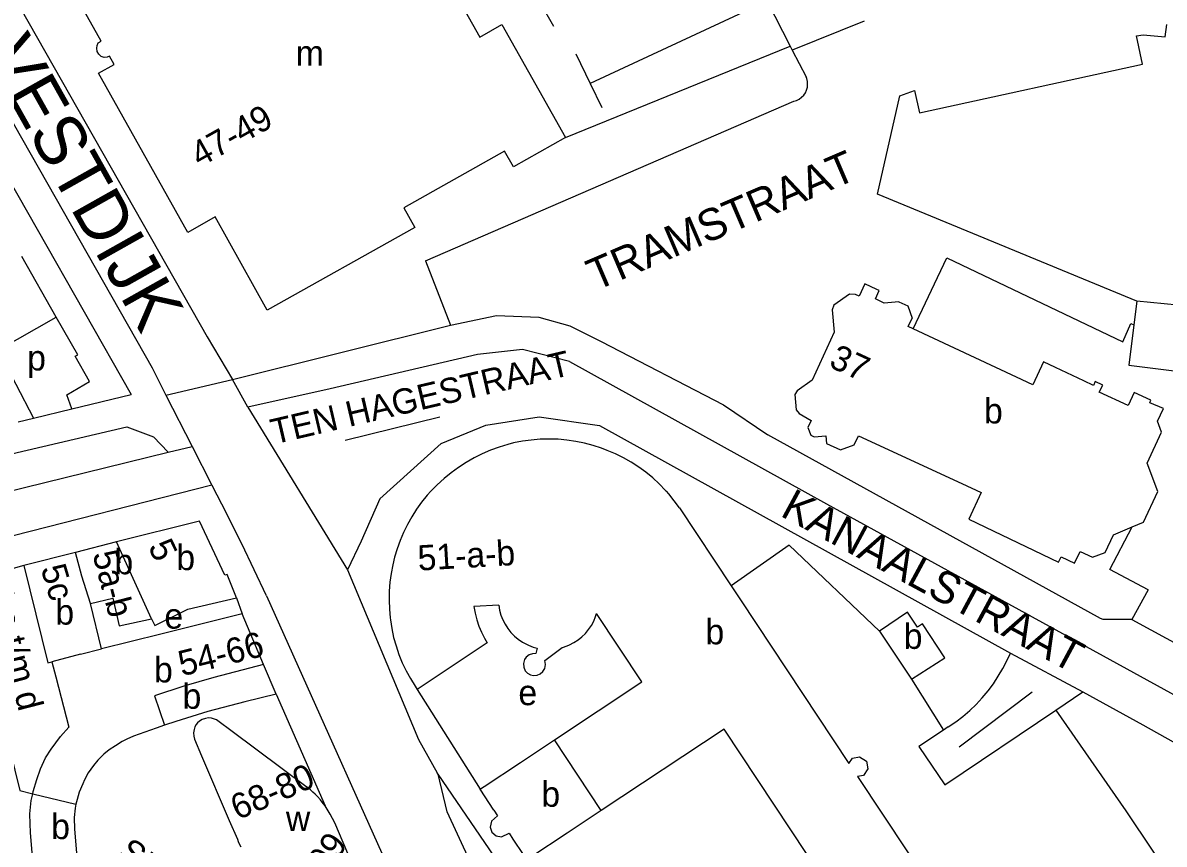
# Model space of a CAD drawing. Extents: x 160673 to 161924, y 382258 to 384145.
# Drawn here: x 161578.5 to 161759.3, y 383169.3 to 383299.3 of the extents above; entities that cross this region are included whole.
import ezdxf

# ---------------------------------------------------------------- set-up
doc = ezdxf.new("R2010")
doc.units = 0
for name, color, linetype in [('BLT_Basislijn', 7, 'Continuous'), ('BLT_Bebouwing', 7, 'Continuous'), ('BLT_Centroide', 7, 'Continuous'), ('BLT_Huisnummer', 7, 'Continuous'), ('BLT_Huisnummer_reeks', 7, 'Continuous'), ('BLT_Onderdoorgang_en_onderverdeling', 7, 'Continuous'), ('BLT_Onderverdeling_panden', 7, 'Continuous'), ('BLT_Straatnaam', 7, 'Continuous'), ('BLT_Straatnaam_hoofdweg', 7, 'Continuous'), ('BLT_Straatnaam_verkleind', 7, 'Continuous'), ('BLT_Vlakafsluiter', 7, 'Continuous')]:
    doc.layers.add(name, color=color, linetype=linetype)

msp = doc.modelspace()

# ---------------------------------------------------------------- linework, layer by layer
at = {"layer": 'BLT_Basislijn'}
for p, q in [((161660.54, 383302.41), (161662.58, 383298.84)), ((161696.43, 383302.76), (161668.39, 383289.75)), ((161696.43, 383302.76), (161700.09, 383295.65)), ((161711.82, 383299.61), (161700.42, 383295.01)), ((161664.48, 383281.17), (161700.09, 383295.65)), ((161700.09, 383295.65), (161700.42, 383295.01)), ((161700.42, 383295.01), (161702.6, 383290.77)), ((161666.15, 383294.42), (161668.39, 383289.75)), ((161668.39, 383289.75), (161670.23, 383285.92)), ((161642.29, 383261.65), (161700.65, 383286.94)), ((161642.29, 383261.65), (161646.26, 383251.49)), ((161574.56, 383247.5), (161583.82, 383252.74)), ((161611.72, 383242.87), (161646.26, 383251.49)), ((161574.56, 383247.5), (161580.19, 383236.75)), ((161586.3, 383238.24), (161595.67, 383240.5)), ((161601.19, 383240.41), (161605.34, 383232.26)), ((161577.8, 383236.18), (161580.19, 383236.75)), ((161580.19, 383236.75), (161586.3, 383238.24)), ((161629.56, 383233.28), (161644.58, 383236.96)), ((161669.86, 383235.59), (161734.98, 383199.52)), ((161599.22, 383233.8), (161601.53, 383231.34)), ((161601.53, 383231.34), (161605.34, 383232.26)), ((161608.47, 383226.14), (161553.47, 383212.15)), ((161608.47, 383226.14), (161610.77, 383221.64)), ((161612.38, 383208.32), (161613.27, 383205.77)), ((161734.19, 383197.92), (161734.98, 383199.52)), ((161734.98, 383199.52), (161746.45, 383193.39)), ((161719.29, 383195.44), (161724.39, 383187.37)), ((161640.99, 383193.81), (161650.96, 383177.99)), ((161738.42, 383193.36), (161726.88, 383184.64)), ((161742.19, 383190.52), (161746.45, 383193.39)), ((161746.45, 383193.39), (161755.96, 383188.2)), ((161618.64, 383193.06), (161626.42, 383175.36)), ((161755.96, 383188.2), (161783.67, 383172.63)), ((161725.13, 383187.86), (161724.39, 383187.37)), ((161644.31, 383180.4), (161644.16, 383180.61)), ((161676.17, 383133.8), (161644.31, 383180.4))]:
    msp.add_line(p, q, dxfattribs=at)
for points in [[(161551.92, 383347.93), (161559.95, 383333.68), (161564.02, 383326.44), (161607.72, 383249.64), (161611.72, 383242.87)], [(161555.31, 383321.52), (161599.03, 383244.7), (161601.19, 383240.41)], [(161550.95, 383319.07), (161550.96, 383319.06), (161595.67, 383240.5)], [(161755, 383255.26), (161713.93, 383272.22), (161717.48, 383287.8), (161719.8, 383288.64), (161720.55, 383285.11), (161755.9, 383292.8), (161754.93, 383297.3), (161756.03, 383297.45), (161759.51, 383297.13), (161759.73, 383299.08)], [(161700.65, 383286.94), (161701.1, 383287.07), (161701.52, 383287.28), (161701.9, 383287.55), (161702.22, 383287.88), (161702.49, 383288.27), (161702.69, 383288.69), (161702.81, 383289.14), (161702.85, 383289.61), (161702.81, 383290.07), (161702.7, 383290.52), (161702.6, 383290.77)], [(161583.82, 383252.74), (161578.34, 383262.37)], [(161586.3, 383238.24), (161585.5, 383240.45), (161589.1, 383242.53), (161586.83, 383246.58), (161587.21, 383246.78), (161583.82, 383252.74)], [(161646.26, 383251.49), (161653.58, 383252.98), (161660.24, 383252.72), (161665.2, 383251.38), (161670.16, 383248.88), (161689.53, 383238.86)], [(161665.14, 383245.7), (161657.68, 383247.6), (161650.55, 383246.83), (161627.21, 383241.39)], [(161665.14, 383245.7), (161705.82, 383223.19), (161827.12, 383156.57)], [(161614.18, 383238.49), (161611.72, 383242.87)], [(161627.21, 383241.39), (161614.18, 383238.49)], [(161689.53, 383238.86), (161696.52, 383234.09)], [(161635.1, 383223.99), (161644.8, 383232.75), (161651.89, 383235.64), (161660.31, 383236.95), (161669.86, 383235.59)], [(161554.12, 383219.74), (161554.47, 383223.02), (161556.42, 383225.91), (161559.99, 383227.18), (161594.98, 383235.4), (161599.22, 383233.8)], [(161754.22, 383204.87), (161749.65, 383204.87), (161749.26, 383205.02), (161696.52, 383234.09)], [(161554.12, 383219.74), (161555.77, 383220.1), (161601.53, 383231.34)], [(161635.1, 383223.99), (161632.12, 383217.27), (161629.94, 383212.71)], [(161617.1, 383208.61), (161613.22, 383216.84), (161610.77, 383221.64)], [(161714.26, 383203), (161699.91, 383216.64), (161690.72, 383210.22)], [(161629.94, 383212.71), (161641.18, 383185.87), (161644.16, 383180.61)], [(161617.1, 383208.61), (161641.78, 383153.62), (161645.56, 383148.03), (161648.67, 383143.25), (161651.84, 383138.51), (161655.08, 383133.82), (161658.38, 383129.17), (161661.75, 383124.57), (161665.19, 383120.02), (161668.68, 383115.51), (161672.25, 383111.06), (161675.87, 383106.65), (161679.55, 383102.3), (161680.29, 383101.44)], [(161725.13, 383187.86), (161726.31, 383188.66), (161727.44, 383189.52), (161728.52, 383190.44), (161729.55, 383191.43), (161730.52, 383192.47), (161731.43, 383193.56), (161732.28, 383194.7), (161733.06, 383195.89), (161733.77, 383197.12), (161734.19, 383197.92)], [(161724.39, 383187.37), (161720.44, 383184.77), (161724.6, 383178.67), (161742.19, 383190.52)], [(161742.19, 383190.52), (161753.26, 383174.57), (161761.69, 383161.98)], [(161651.29, 383162.43), (161645.75, 383174.39), (161644.31, 383180.4)]]:
    msp.add_lwpolyline(points, dxfattribs=at)
at = {"layer": 'BLT_Bebouwing'}
for p, q in [((161664.48, 383281.17), (161656.25, 383276.55)), ((161717.32, 383255.17), (161718.72, 383254.51)), ((161718.72, 383254.51), (161719.41, 383252.6)), ((161705.82, 383232.74), (161708.05, 383231.71)), ((161708.05, 383231.71), (161710.24, 383232.52)), ((161680.33, 383225.32), (161680.47, 383225.17)), ((161682.55, 383222.53), (161690.72, 383210.22)), ((161606.5, 383220.45), (161593.38, 383217.14)), ((161593.38, 383217.14), (161586.86, 383215.49)), ((161690.72, 383210.22), (161692.21, 383207.98)), ((161653.9, 383207.13), (161649.99, 383206.9)), ((161718.66, 383206.03), (161714.26, 383203)), ((161613.27, 383205.77), (161600.37, 383202.52)), ((161616.66, 383197.74), (161613.27, 383205.77)), ((161714.26, 383203), (161719.29, 383195.44)), ((161652.1, 383201.17), (161640.99, 383193.81)), ((161618.64, 383193.06), (161616.66, 383197.74)), ((161583.72, 383195.81), (161585.78, 383187.83)), ((161653.15, 383174.67), (161650.96, 383177.99))]:
    msp.add_line(p, q, dxfattribs=at)
for points in [[(161642.35, 383312.28), (161650.89, 383297.09), (161654.42, 383299.07), (161664.48, 383281.17)], [(161640.6, 383266.93), (161617.24, 383253.87), (161609, 383268.61), (161604.67, 383266.17), (161590.52, 383291.38), (161592.99, 383292.77), (161592.27, 383294.05), (161591.88, 383293.89), (161591.41, 383293.86), (161590.95, 383294.03), (161590.53, 383294.36), (161590.28, 383294.83), (161590.22, 383295.34), (161590.3, 383295.77), (161590.47, 383296.19), (161590.93, 383296.45), (161586.36, 383304.56), (161588.37, 383305.7)], [(161656.25, 383276.55), (161654.85, 383279.03), (161638.86, 383270.04), (161640.6, 383266.93)], [(161719.56, 383250.9), (161724.9, 383262.13), (161752.81, 383248.84), (161754.04, 383251.73), (161754.53, 383251.51)], [(161713.83, 383257.11), (161711.9, 383258.02), (161710.99, 383256.07), (161710.43, 383256.33), (161709.48, 383256.36), (161707, 383254.63), (161706.76, 383253.9), (161707.06, 383250.37), (161703.55, 383242.76), (161701.2, 383241.1), (161700.8, 383240.48), (161701.02, 383238.05), (161701.53, 383237.5), (161703.39, 383236.37), (161702.89, 383235.27), (161703.33, 383234.07), (161703.89, 383233.8), (161705.71, 383233.97), (161705.82, 383232.74)], [(161717.32, 383255.17), (161714.99, 383254.97), (161713.58, 383255.63), (161714.2, 383256.94), (161713.83, 383257.11)], [(161755, 383255.26), (161754.53, 383251.51)], [(161765.85, 383254.2), (161755, 383255.26)], [(161719.56, 383250.9), (161718.79, 383251.26), (161719.41, 383252.6)], [(161746.63, 383242.64), (161742.1, 383244.77)], [(161759.21, 383238.3), (161757.05, 383239.2), (161757.23, 383239.6), (161754.58, 383240.82), (161753.62, 383238.74), (161749.06, 383240.85), (161749.59, 383241.99), (161748.41, 383242.54), (161748.13, 383241.94), (161746.63, 383242.64)], [(161754.28, 383219.55), (161756.08, 383220.3), (161758.31, 383225.12), (161756.65, 383229.63), (161758.91, 383234.53), (161758.27, 383236.27), (161759.21, 383238.3)], [(161670.2, 383231.98), (161668.86, 383232.42), (161667.49, 383232.78), (161666.11, 383233.06), (161664.71, 383233.27), (161663.3, 383233.4), (161661.88, 383233.44), (161660.47, 383233.41), (161659.06, 383233.29), (161657.66, 383233.1), (161656.27, 383232.83), (161655.36, 383232.6)], [(161710.24, 383232.52), (161710.91, 383233.97), (161727.28, 383226.39)], [(161655.36, 383232.6), (161653.98, 383232.18), (161652.62, 383231.68), (161651.29, 383231.11), (161650, 383230.46), (161648.75, 383229.74), (161647.53, 383228.96), (161646.36, 383228.1), (161645.24, 383227.19), (161644.18, 383226.21), (161643.17, 383225.18), (161642.58, 383224.53)], [(161680.33, 383225.32), (161679.35, 383226.33), (161678.31, 383227.29), (161677.22, 383228.18), (161676.08, 383229.01), (161674.9, 383229.77), (161673.67, 383230.47), (161672.4, 383231.09), (161671.11, 383231.64), (161670.2, 383231.98)], [(161727.28, 383226.39), (161730.34, 383224.98), (161728.4, 383220.77), (161742.61, 383213.93), (161743, 383214.78), (161745.15, 383213.78), (161746.02, 383215.66), (161747.99, 383214.75), (161750, 383215.49), (161751.3, 383218.3), (161754.28, 383219.55)], [(161642.58, 383224.53), (161641.7, 383223.45), (161640.88, 383222.32), (161640.12, 383221.14), (161639.44, 383219.93), (161638.82, 383218.67), (161638.28, 383217.39), (161637.81, 383216.07), (161637.42, 383214.73), (161637.14, 383213.55)], [(161682.55, 383222.53), (161681.73, 383223.67), (161680.84, 383224.76), (161680.47, 383225.17)], [(161610.52, 383211.91), (161606.5, 383220.45)], [(161756.8, 383209.57), (161750.71, 383212.81), (161754.28, 383219.55)], [(161586.86, 383215.49), (161578.69, 383213.41)], [(161578.69, 383213.41), (161574.95, 383212.36), (161574.91, 383212.48), (161562.22, 383209.32), (161562.24, 383209)], [(161637.14, 383213.55), (161636.87, 383212.16), (161636.68, 383210.76), (161636.56, 383209.35), (161636.53, 383207.94), (161636.58, 383206.53), (161636.7, 383205.12), (161636.74, 383204.82)], [(161612.38, 383208.32), (161610.88, 383212), (161610.52, 383211.91)], [(161589.23, 383207.38), (161592.8, 383208.27), (161593.76, 383203.85), (161598.91, 383204.97)], [(161598.91, 383204.97), (161599.43, 383203.9), (161604.68, 383206.5), (161612.38, 383208.32)], [(161692.21, 383207.98), (161709.38, 383182.09), (161709.93, 383182.91), (161711.09, 383183.14), (161712.15, 383182.42), (161712.4, 383181.2), (161711.69, 383180.19), (161710.74, 383180.02), (161726.68, 383155.97)], [(161756.8, 383209.57), (161754.22, 383204.87)], [(161591, 383200.24), (161589.23, 383207.38)], [(161649.99, 383206.9), (161650.17, 383205.86), (161650.43, 383204.83), (161650.76, 383203.83), (161651.17, 383202.85), (161651.65, 383201.91), (161652.1, 383201.17)], [(161653.9, 383207.13), (161654.04, 383206.35), (161654.26, 383205.58), (161654.55, 383204.83), (161654.91, 383204.12), (161655.34, 383203.45), (161655.84, 383202.82), (161656.4, 383202.25), (161657.01, 383201.74), (161657.67, 383201.29), (161657.89, 383201.16)], [(161721.04, 383204.19), (161720.26, 383203.68), (161718.66, 383206.03)], [(161636.74, 383204.82), (161636.96, 383203.42), (161637.26, 383202.04), (161637.64, 383200.68), (161638.1, 383199.34), (161638.63, 383198.03), (161639.23, 383196.75), (161639.91, 383195.51), (161640.65, 383194.31), (161640.99, 383193.81)], [(161662.74, 383185.8), (161676.57, 383195), (161669.4, 383205.8)], [(161665.1, 383200.85), (161665.8, 383201.2), (161666.47, 383201.63), (161667.08, 383202.12), (161667.64, 383202.67), (161668.15, 383203.28), (161668.59, 383203.93), (161668.96, 383204.62), (161669.26, 383205.35), (161669.4, 383205.8)], [(161719.29, 383195.44), (161724.56, 383198.82), (161721.04, 383204.19)], [(161754.22, 383204.87), (161809.76, 383174.68)], [(161600.37, 383202.52), (161591, 383200.24)], [(161657.89, 383201.16), (161658.6, 383200.8), (161659.34, 383200.51), (161660.01, 383200.33), (161659.8, 383199.47), (161659.25, 383199.45), (161658.73, 383199.27), (161658.26, 383198.9), (161658, 383198.51), (161657.82, 383197.92), (161657.87, 383197.31), (161658.12, 383196.74), (161658.47, 383196.37), (161658.94, 383196.1), (161659.44, 383195.99), (161659.99, 383196.04), (161660.46, 383196.24), (161660.9, 383196.61), (161661.2, 383197.13), (161661.31, 383197.76), (161661.2, 383198.35), (161663.95, 383200.42), (161664.02, 383200.44), (161664.77, 383200.7), (161665.1, 383200.85)], [(161574.02, 383193.88), (161578.02, 383177.79), (161580.09, 383177.28)], [(161618.64, 383193.06), (161613.66, 383191.83), (161607.81, 383190.3), (161602.75, 383188.72), (161600.94, 383188.11)], [(161600.94, 383188.11), (161599.65, 383187.67), (161596.04, 383186.39), (161594.97, 383185.92), (161594.25, 383185.54), (161593.17, 383184.89), (161592.18, 383184.21), (161591.36, 383183.52), (161590.42, 383182.57), (161589.72, 383181.74), (161588.89, 383180.6), (161588.27, 383179.5), (161588, 383178.87), (161587.42, 383177.52), (161587.1, 383176.39), (161586.93, 383175.61)], [(161623.35, 383178.44), (161611.7, 383187.13), (161609.42, 383188.83), (161609.2, 383188.97), (161608.89, 383189.11), (161608.43, 383189.24), (161607.91, 383189.28), (161607.43, 383189.21), (161606.92, 383189.03), (161606.5, 383188.76), (161606.21, 383188.5), (161605.99, 383188.22), (161605.78, 383187.86), (161605.64, 383187.46), (161605.56, 383186.9), (161605.6, 383186.37), (161605.73, 383185.93), (161606.84, 383183.3), (161611.23, 383173.02)], [(161580.09, 383177.28), (161580.17, 383177.62), (161580.72, 383179.54), (161581.33, 383181.24), (161582.11, 383182.96), (161582.98, 383184.35), (161584.5, 383186.36), (161585.78, 383187.83)], [(161688.57, 383146.81), (161708.05, 383159.68), (161689.63, 383187.5), (161670.15, 383174.62)], [(161650.96, 383177.99), (161651.33, 383178.24), (161651.61, 383178.42), (161657.35, 383182.23), (161662.74, 383185.8)], [(161579.64, 383174.06), (161579.64, 383174.09), (161579.86, 383176.23), (161580.09, 383177.28)], [(161626.42, 383175.36), (161625.94, 383175.96), (161625.67, 383176.3), (161625.2, 383176.83), (161624.83, 383177.2), (161624.48, 383177.53), (161624.08, 383177.88), (161623.75, 383178.14), (161623.35, 383178.44)], [(161586.93, 383175.61), (161586.79, 383174.97), (161586.65, 383173.49), (161586.7, 383171.67), (161587.32, 383164.2)], [(161634.69, 383156.74), (161627.93, 383172.69), (161627.23, 383174.06), (161626.42, 383175.36)], [(161580.06, 383167.33), (161579.72, 383171.08), (161579.64, 383174.06)], [(161653.15, 383174.67), (161653.69, 383173.8), (161652.79, 383172.96), (161652.55, 383172.01), (161652.84, 383171.19), (161653.48, 383170.62), (161654.34, 383170.46), (161655.54, 383171.01), (161656.15, 383170.1)], [(161670.15, 383174.62), (161664.76, 383171.04), (161658.99, 383167.23), (161658.36, 383166.81)], [(161611.23, 383173.02), (161612.5, 383170.06), (161612.64, 383169.69), (161612.81, 383169.34), (161613.04, 383168.88)], [(161656.15, 383170.1), (161657.79, 383167.68), (161658.36, 383166.81)]]:
    msp.add_lwpolyline(points, dxfattribs=at)
at = {"layer": 'BLT_Onderdoorgang_en_onderverdeling'}
for p, q in [((161670.15, 383174.62), (161662.74, 383185.8)), ((161580.09, 383177.28), (161586.93, 383175.61))]:
    msp.add_line(p, q, dxfattribs=at)
msp.add_lwpolyline([(161616.66, 383197.74), (161608.78, 383195.67), (161604.04, 383194.3), (161599.35, 383192.77), (161600.94, 383188.11)], dxfattribs=at)
at = {"layer": 'BLT_Onderverdeling_panden'}
for p, q in [((161598.91, 383204.97), (161593.38, 383217.14)), ((161583.11, 383198.17), (161583.72, 383195.81))]:
    msp.add_line(p, q, dxfattribs=at)
for points in [[(161754.53, 383251.51), (161753.72, 383245.13), (161773.6, 383242.67), (161773.66, 383243.24), (161808.11, 383239.29)], [(161742.1, 383244.77), (161740.2, 383245.66), (161738.52, 383242.04), (161735.92, 383243.24), (161719.56, 383250.9)], [(161587.86, 383211.75), (161586.86, 383215.49)], [(161578.69, 383213.41), (161582.47, 383198), (161583.11, 383198.17)], [(161589.23, 383207.38), (161587.86, 383211.75)], [(161587.65, 383199.37), (161583.11, 383198.17)], [(161587.65, 383199.37), (161591, 383200.24)]]:
    msp.add_lwpolyline(points, dxfattribs=at)
at = {"layer": 'BLT_Vlakafsluiter'}
for p, q in [((161601.19, 383240.41), (161611.72, 383242.87)), ((161614.18, 383238.49), (161629.94, 383212.71)), ((161605.34, 383232.26), (161608.47, 383226.14))]:
    msp.add_line(p, q, dxfattribs=at)

# ---------------------------------------------------------------- texts
at = {"layer": 'BLT_Centroide'}
for s, p in [('m', (161621.76, 383292.56)), ('p', (161579.2, 383244.3)), ('b', (161730.79, 383235.91)), ('b', (161602.83, 383212.69)), ('b', (161593.03, 383212.03)), ('b', (161583.67, 383204.06)), ('e', (161600.94, 383203.42)), ('b', (161686.66, 383200.94)), ('b', (161718.07, 383200.22)), ('b', (161599.3, 383194.91)), ('b', (161603.82, 383190.73)), ('e', (161657.02, 383191.3)), ('b', (161660.66, 383175.22)), ('b', (161583.01, 383170.1)), ('w', (161620.19, 383171.38))]:
    msp.add_text(s, height=4, dxfattribs=at).set_placement(p)
at = {"layer": 'BLT_Huisnummer'}
for s, rotation, p in [('37', 335.1647, (161706.03, 383244.96)), ('5', 295.4568, (161598.3, 383216.41)), ('5c', 286.4568, (161581.33, 383212.98))]:
    msp.add_text(s, height=4, rotation=rotation, dxfattribs=at).set_placement(p)
at = {"layer": 'BLT_Huisnummer_reeks'}
for s, rotation, p in [('47-49', 29.3274, (161606.55, 383276.41)), ('51-a-b', 3.3476, (161641.17, 383212.6)), ('5a-b', 284.7614, (161589.53, 383215.26)), ('7-a t/m d', 284.4309, (161572.66, 383210.57)), ('54-66', 13.9556, (161603.71, 383195.86)), ('68-80', 23.599, (161612.55, 383173.06)), ('9-99', 53.1442, (161623.69, 383160.63))]:
    msp.add_text(s, height=4, rotation=rotation, dxfattribs=at).set_placement(p)
at = {"layer": 'BLT_Straatnaam'}
for s, rotation, p in [('TRAMSTRAAT', 23.1876, (161669.26, 383256.86)), ('KANAALSTRAAT', 331.6449, (161698.34, 383221.36))]:
    msp.add_text(s, height=5, rotation=rotation, dxfattribs=at).set_placement(p)
at = {"layer": 'BLT_Straatnaam_hoofdweg'}
msp.add_text('VESTDIJK', height=8, rotation=299.3368, dxfattribs=at).set_placement((161572.28, 383294.42))
at = {"layer": 'BLT_Straatnaam_verkleind'}
for s, rotation, p in [('TEN HAGESTRAAT', 13.1608, (161618.33, 383232.58)), ('SMALLE HAVEN', 323.024, (161593.29, 383167.37))]:
    msp.add_text(s, height=4, rotation=rotation, dxfattribs=at).set_placement(p)

doc.saveas('drawing.dxf')
